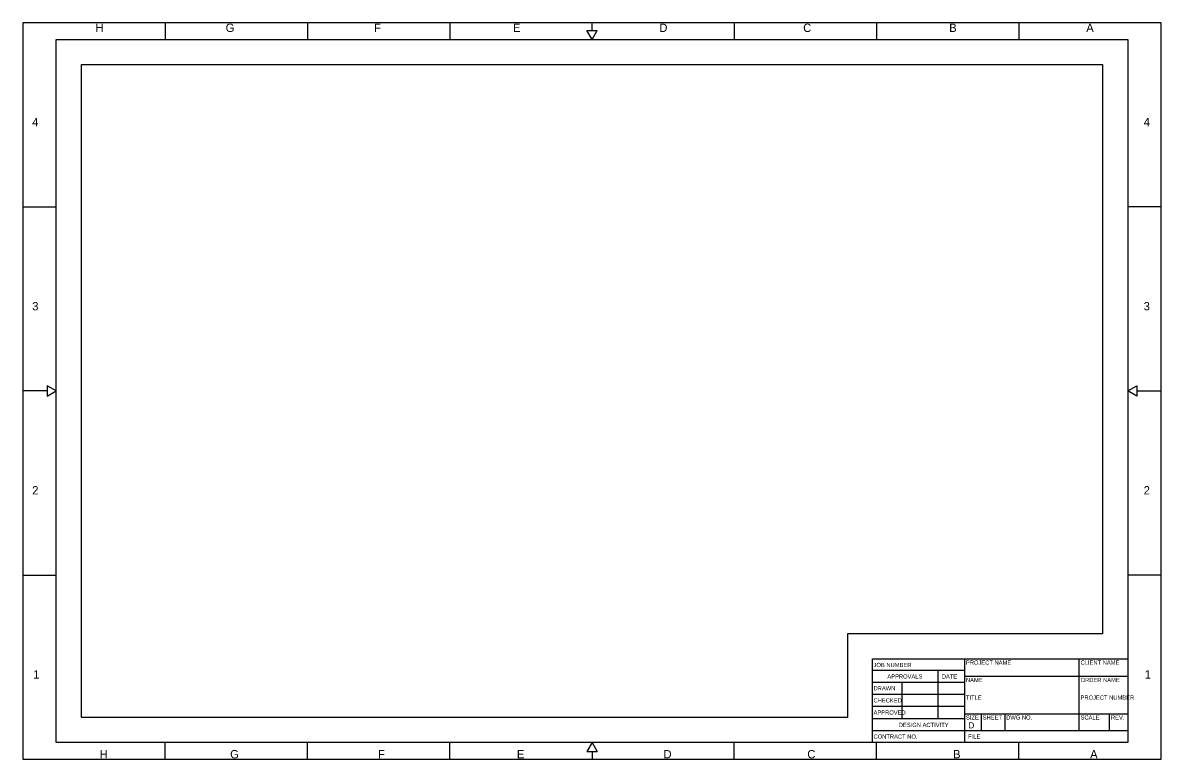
# Model space of a CAD drawing. Extents: x 0 to 34, y 0 to 22.
import ezdxf

# ---------------------------------------------------------------- set-up
doc = ezdxf.new("R2010")
doc.units = 0
for name, color, linetype in [('Border', 7, 'Continuous'), ('BorderPlot', 7, 'Continuous'), ('ClipShape', 7, 'Continuous'), ('TitleBlock', 7, 'Continuous'), ('TitleBlockText', 7, 'Continuous')]:
    doc.layers.add(name, color=color, linetype=linetype)

# ---------------------------------------------------------------- blocks, each defined once
blk = doc.blocks.new('DC-ANSI-D_SC12')
at = {"layer": 'Border'}
for p, q in [((0.3542, 1.8333), (0.3542, 1.7917)), ((0.7083, 1.8333), (0.7083, 1.7917)), ((1.0625, 1.8333), (1.0625, 1.7917)), ((1.4167, 1.7917), (1.4036, 1.8143)), ((1.4036, 1.8143), (1.4297, 1.8143)), ((1.4167, 1.8143), (1.4167, 1.8333)), ((1.4167, 1.7917), (1.4297, 1.8143)), ((1.7708, 1.8333), (1.7708, 1.7917)), ((2.125, 1.8333), (2.125, 1.7917)), ((2.4792, 1.8333), (2.4792, 1.7917)), ((0, 1.375), (0.0833, 1.375)), ((2.8333, 1.375), (2.75, 1.375)), ((0.0607, 0.9167), (0, 0.9167)), ((0.0833, 0.9167), (0.0607, 0.9297)), ((0.0607, 0.9297), (0.0607, 0.9036)), ((0.0607, 0.9036), (0.0833, 0.9167)), ((2.75, 0.9167), (2.7726, 0.9297)), ((2.7726, 0.9036), (2.75, 0.9167)), ((2.7726, 0.9297), (2.7726, 0.9036)), ((2.7726, 0.9167), (2.8333, 0.9167)), ((0, 0.4583), (0.0833, 0.4583)), ((2.8333, 0.4583), (2.75, 0.4583)), ((0.3542, 0), (0.3542, 0.0417)), ((0.7083, 0), (0.7083, 0.0417)), ((1.0625, 0), (1.0625, 0.0417)), ((1.4167, 0.0417), (1.4036, 0.0191)), ((1.4167, 0.0417), (1.4297, 0.0191)), ((1.7708, 0), (1.7708, 0.0417)), ((2.125, 0), (2.125, 0.0417)), ((2.4792, 0), (2.4792, 0.0417)), ((1.4036, 0.0191), (1.4297, 0.0191)), ((1.4167, 0.0191), (1.4167, 0))]:
    blk.add_line(p, q, dxfattribs=at)
blk.add_lwpolyline([(2.75, 0.0417), (0.0833, 0.0417), (0.0833, 1.7917), (2.75, 1.7917)], close=True, dxfattribs=at)
at = {"layer": 'BorderPlot'}
blk.add_lwpolyline([(0, 0), (2.8333, 0), (2.8333, 1.8333), (0, 1.8333)], close=True, dxfattribs=at)
at = {"layer": 'ClipShape'}
for p, q in [((0.1458, 0.1042), (0.1458, 1.7292)), ((0.1458, 1.7292), (2.6875, 1.7292)), ((2.6875, 1.7292), (2.6875, 0.3125)), ((2.6875, 0.3125), (2.0525, 0.3125)), ((2.0525, 0.3125), (2.0525, 0.1042)), ((2.0525, 0.1042), (0.1458, 0.1042))]:
    blk.add_line(p, q, dxfattribs=at)
at = {"layer": 'TitleBlock'}
for p, q in [((2.115, 0.0417), (2.115, 0.25)), ((2.115, 0.25), (2.75, 0.25)), ((2.3442, 0.0417), (2.3442, 0.25)), ((2.6293, 0.0717), (2.6293, 0.25)), ((2.115, 0.2217), (2.3442, 0.2217)), ((2.2782, 0.1017), (2.2782, 0.2217)), ((2.3442, 0.2067), (2.75, 0.2067)), ((2.115, 0.1917), (2.3442, 0.1917)), ((2.1883, 0.1017), (2.1883, 0.1917)), ((2.115, 0.1617), (2.3442, 0.1617)), ((2.115, 0.1317), (2.3442, 0.1317)), ((2.3442, 0.1133), (2.75, 0.1133)), ((2.3858, 0.0717), (2.3858, 0.1133)), ((2.4451, 0.0717), (2.4451, 0.1133)), ((2.7049, 0.0717), (2.7049, 0.1133)), ((2.115, 0.1017), (2.3442, 0.1017)), ((2.115, 0.0717), (2.75, 0.0717)), ((2.75, 0.0417), (2.75, 0.0417))]:
    blk.add_line(p, q, dxfattribs=at)
at = {"layer": 'Border'}
for s, p in [('H', (0.1808, 1.8104)), ('G', (0.5049, 1.8104)), ('F', (0.8743, 1.8104)), ('E', (1.2202, 1.8104)), ('D', (1.5843, 1.8104)), ('C', (1.9423, 1.8104)), ('B', (2.3057, 1.8104)), ('A', (2.6468, 1.8104)), ('4', (0.0235, 1.5758)), ('4', (2.7897, 1.5758)), ('3', (0.0235, 1.1174)), ('3', (2.7897, 1.1174)), ('2', (0.0235, 0.6591)), ('2', (2.7897, 0.6591)), ('1', (0.0261, 0.2008)), ('1', (2.7923, 0.2008)), ('H', (0.1912, 0.0021)), ('G', (0.5161, 0.0021)), ('F', (0.8839, 0.0021)), ('E', (1.2298, 0.0021)), ('D', (1.5946, 0.0021)), ('C', (1.9526, 0.0021)), ('B', (2.3153, 0.0021)), ('A', (2.6564, 0.0021))]:
    blk.add_text(s, height=0.0208, dxfattribs=at).set_placement(p)
at = {"layer": 'TitleBlock'}
blk.add_text('D', height=0.0156, dxfattribs=at).set_placement((2.3532, 0.0766))
at = {"layer": 'TitleBlockText'}
for s, height, p in [('JOB NUMBER', 0.01042, (2.1173, 0.2295)), ('PROJECT NAME', 0.010417, (2.3473, 0.2355)), ('CLIENT NAME', 0.010417, (2.6326, 0.2355)), ('APPROVALS', 0.01042, (2.1517, 0.2008)), ('DATE', 0.01042, (2.2872, 0.2008)), ('NAME', 0.01042, (2.3473, 0.1921)), ('ORDER NAME', 0.01042, (2.6326, 0.1921)), ('DRAWN', 0.01042, (2.1173, 0.1715)), ('CHECKED', 0.01042, (2.1173, 0.1413)), ('TITLE', 0.01042, (2.3473, 0.1483)), ('PROJECT NUMBER', 0.010417, (2.6326, 0.1483)), ('APPROVED', 0.01042, (2.1173, 0.1111)), ('DESIGN ACTIVITY', 0.010417, (2.1802, 0.0803)), ('SIZE', 0.01042, (2.3473, 0.0988)), ('SHEET', 0.01042, (2.389, 0.0988)), ('DWG NO.', 0.01042, (2.4474, 0.0988)), ('SCALE', 0.01042, (2.6326, 0.0988)), ('REV.', 0.01042, (2.7082, 0.0988)), ('CONTRACT NO.', 0.010417, (2.1173, 0.0512)), ('FILE', 0.01042, (2.3528, 0.0513))]:
    blk.add_text(s, height=height, dxfattribs=at).set_placement(p)

msp = doc.modelspace()

# ---------------------------------------------------------------- block references
at = {"xscale": 12, "yscale": 12}
msp.add_blockref('DC-ANSI-D_SC12', (0, 0), dxfattribs=at)

doc.saveas('drawing.dxf')
